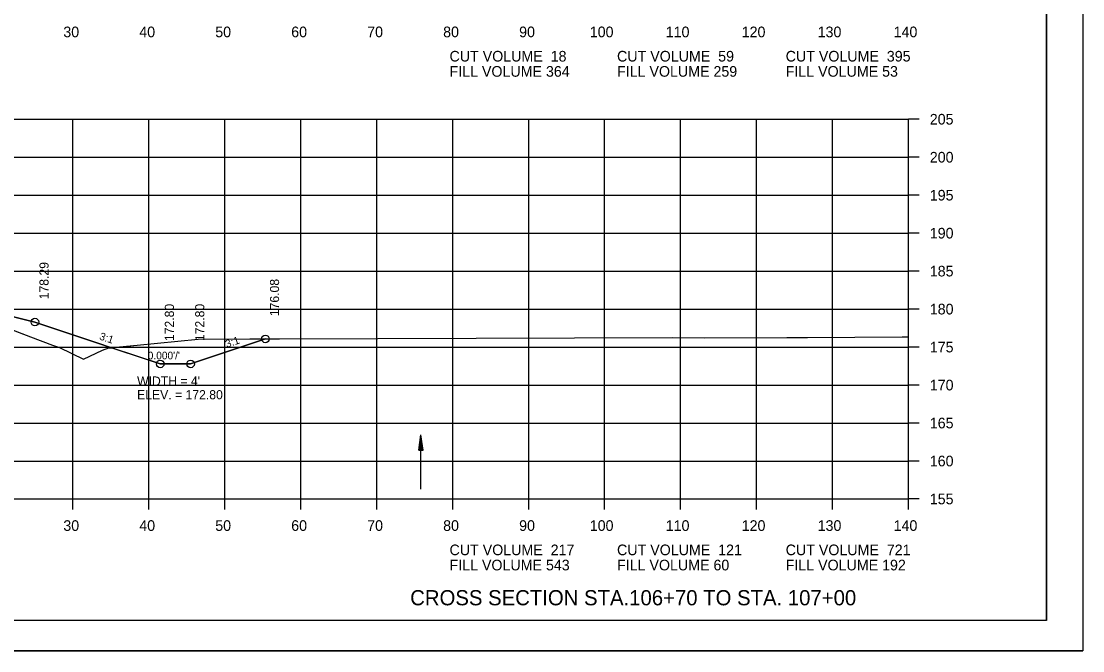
# Model space of a CAD drawing. Extents: x 1372132 to 1372465, y 380083 to 381790.
# Drawn here: x 1372325.2 to 1372464.9, y 380723.5 to 380806.4 of the extents above; entities that cross this region are included whole.
import ezdxf

# ---------------------------------------------------------------- set-up
doc = ezdxf.new("R2010")
doc.units = 0
for name, color, linetype in [('R_Axis', 7, 'Continuous'), ('R_Axis Annot', 7, 'Continuous'), ('R_Border', 7, 'Continuous'), ('R_Dimension', 7, 'Continuous'), ('R_Draft', 7, 'Continuous'), ('R_Exist Surface', 7, 'Continuous'), ('R_Fin Surface', 7, 'Continuous'), ('R_Grid', 7, 'Continuous'), ('R_No Plot', 7, 'Continuous'), ('R_Xsect Elev', 7, 'Continuous'), ('R_Xsect Slope', 7, 'Continuous')]:
    doc.layers.add(name, color=color, linetype=linetype)

msp = doc.modelspace()

# ---------------------------------------------------------------- linework, layer by layer
at = {"layer": 'R_Axis'}
for p, q in [((1372442.01, 380743.49), (1372442.01, 380793.49)), ((1372443.41, 380793.49), (1372442.01, 380793.49)), ((1372443.41, 380788.49), (1372442.01, 380788.49)), ((1372443.41, 380783.49), (1372442.01, 380783.49)), ((1372443.41, 380778.49), (1372442.01, 380778.49)), ((1372443.41, 380773.49), (1372442.01, 380773.49)), ((1372443.41, 380768.49), (1372442.01, 380768.49)), ((1372443.41, 380763.49), (1372442.01, 380763.49)), ((1372443.41, 380758.49), (1372442.01, 380758.49)), ((1372443.41, 380753.49), (1372442.01, 380753.49)), ((1372443.41, 380748.49), (1372442.01, 380748.49)), ((1372162.01, 380743.49), (1372442.01, 380743.49)), ((1372332.01, 380742.09), (1372332.01, 380743.49)), ((1372342.01, 380742.09), (1372342.01, 380743.49)), ((1372352.01, 380742.09), (1372352.01, 380743.49)), ((1372362.01, 380742.09), (1372362.01, 380743.49)), ((1372372.01, 380742.09), (1372372.01, 380743.49)), ((1372382.01, 380742.09), (1372382.01, 380743.49)), ((1372392.01, 380742.09), (1372392.01, 380743.49)), ((1372402.01, 380742.09), (1372402.01, 380743.49)), ((1372412.01, 380742.09), (1372412.01, 380743.49)), ((1372422.01, 380742.09), (1372422.01, 380743.49)), ((1372432.01, 380742.09), (1372432.01, 380743.49)), ((1372442.01, 380742.09), (1372442.01, 380743.49)), ((1372443.41, 380743.49), (1372442.01, 380743.49))]:
    msp.add_line(p, q, dxfattribs=at)
at = {"layer": 'R_Border'}
for q in [(1372460.19, 380932.95), (1372144.01, 380727.49)]:
    msp.add_line((1372460.19, 380727.49), q, dxfattribs=at)
at = {"layer": 'R_Dimension'}
for p, q in [((1372377.53, 380749.93), (1372377.83, 380751.93)), ((1372377.53, 380749.93), (1372377.83, 380751.93)), ((1372377.58, 380749.93), (1372377.83, 380751.6)), ((1372377.58, 380749.93), (1372377.83, 380751.6)), ((1372378.13, 380749.93), (1372377.83, 380751.93)), ((1372378.13, 380749.93), (1372377.83, 380751.93)), ((1372378.08, 380749.93), (1372377.83, 380751.6)), ((1372378.08, 380749.93), (1372377.83, 380751.6)), ((1372377.64, 380749.93), (1372377.83, 380751.25)), ((1372377.64, 380749.93), (1372377.83, 380751.25)), ((1372377.69, 380749.93), (1372377.83, 380750.92)), ((1372377.69, 380749.93), (1372377.83, 380750.92)), ((1372377.74, 380749.93), (1372377.83, 380750.58)), ((1372377.74, 380749.93), (1372377.83, 380750.58)), ((1372377.79, 380749.93), (1372377.83, 380750.25)), ((1372377.79, 380749.93), (1372377.83, 380750.25)), ((1372378.03, 380749.93), (1372377.83, 380751.25)), ((1372378.03, 380749.93), (1372377.83, 380751.25)), ((1372377.98, 380749.93), (1372377.83, 380750.92)), ((1372377.98, 380749.93), (1372377.83, 380750.92)), ((1372377.93, 380749.93), (1372377.83, 380750.58)), ((1372377.93, 380749.93), (1372377.83, 380750.58)), ((1372377.88, 380749.93), (1372377.83, 380750.25)), ((1372377.88, 380749.93), (1372377.83, 380750.25)), ((1372377.53, 380749.93), (1372378.13, 380749.93)), ((1372377.53, 380749.93), (1372378.13, 380749.93))]:
    msp.add_line(p, q, dxfattribs=at)
at = {"layer": 'R_Draft'}
msp.add_line((1372377.83, 380744.79), (1372377.83, 380751.93), dxfattribs=at)
at = {"layer": 'R_Exist Surface'}
msp.add_lwpolyline([(1372316.46, 380768.64), (1372326.44, 380764.85), (1372329.31, 380763.76), (1372330.26, 380763.44), (1372333.41, 380761.92), (1372335.9, 380763.07), (1372336.73, 380763.38), (1372340.45, 380763.74), (1372348.48, 380764.54), (1372355.29, 380764.56), (1372359.2, 380764.57), (1372410.98, 380764.76), (1372415.19, 380764.73), (1372425.99, 380764.77), (1372428.73, 380764.77), (1372441.16, 380764.82), (1372442.01, 380764.82)], dxfattribs=at)
at = {"layer": 'R_Fin Surface'}
msp.add_lwpolyline([(1372239.2, 380762.85), (1372244.03, 380761.25), (1372248.2, 380759.84), (1372256.2, 380759.84), (1372266.67, 380763.32), (1372277.01, 380766.78), (1372282.65, 380768.19), (1372287.01, 380769.28), (1372291.01, 380769.44), (1372302.01, 380769.66), (1372313.01, 380769.44), (1372317.01, 380769.28), (1372321.38, 380768.19), (1372327.01, 380766.78), (1372335.18, 380764.05), (1372343.51, 380761.28), (1372347.51, 380761.28), (1372352.36, 380762.91), (1372357.35, 380764.56)], dxfattribs=at)
at = {"layer": 'R_Grid'}
for p, q in [((1372162.01, 380793.49), (1372442.01, 380793.49)), ((1372332.01, 380743.49), (1372332.01, 380793.49)), ((1372342.01, 380743.49), (1372342.01, 380793.49)), ((1372352.01, 380743.49), (1372352.01, 380793.49)), ((1372362.01, 380743.49), (1372362.01, 380793.49)), ((1372372.01, 380743.49), (1372372.01, 380793.49)), ((1372382.01, 380743.49), (1372382.01, 380793.49)), ((1372392.01, 380743.49), (1372392.01, 380793.49)), ((1372402.01, 380743.49), (1372402.01, 380793.49)), ((1372412.01, 380743.49), (1372412.01, 380793.49)), ((1372422.01, 380743.49), (1372422.01, 380793.49)), ((1372432.01, 380743.49), (1372432.01, 380793.49)), ((1372442.01, 380743.49), (1372442.01, 380793.49)), ((1372162.01, 380788.49), (1372442.01, 380788.49)), ((1372162.01, 380783.49), (1372442.01, 380783.49)), ((1372162.01, 380778.49), (1372442.01, 380778.49)), ((1372162.01, 380773.49), (1372442.01, 380773.49)), ((1372162.01, 380768.49), (1372442.01, 380768.49)), ((1372162.01, 380763.49), (1372442.01, 380763.49)), ((1372162.01, 380758.49), (1372442.01, 380758.49)), ((1372162.01, 380753.49), (1372442.01, 380753.49)), ((1372162.01, 380748.49), (1372442.01, 380748.49)), ((1372162.01, 380743.49), (1372442.01, 380743.49))]:
    msp.add_line(p, q, dxfattribs=at)
at = {"layer": 'R_No Plot'}
msp.add_line((1372131.61, 380723.51), (1372464.95, 380723.51), dxfattribs=at)
for points in [[(1372131.61, 380936.84), (1372464.95, 380936.84), (1372464.95, 380723.5), (1372131.61, 380723.5)], [(1372377.93, 380932.95), (1372377.93, 380923.07), (1372413.67, 380923.07), (1372413.67, 380920.15), (1372436.87, 380920.15), (1372436.87, 380895.81), (1372460.19, 380895.81), (1372460.19, 380727.49), (1372144.01, 380727.49), (1372144.01, 380932.95)], [(1372317.43, 380768.27), (1372326.44, 380764.85), (1372329.31, 380763.76), (1372330.26, 380763.44), (1372333.41, 380761.92), (1372335.9, 380763.07), (1372336.73, 380763.38), (1372337.09, 380763.41), (1372335.18, 380764.05), (1372327.01, 380766.78), (1372321.38, 380768.19)], [(1372337.09, 380763.41), (1372340.45, 380763.74), (1372348.48, 380764.54), (1372355.29, 380764.56), (1372357.35, 380764.56), (1372352.36, 380762.91), (1372347.51, 380761.28), (1372343.51, 380761.28)]]:
    msp.add_lwpolyline(points, close=True, dxfattribs=at)
for centre in [(1372327.01, 380766.78), (1372357.35, 380764.56), (1372343.51, 380761.28), (1372347.51, 380761.28)]:
    msp.add_circle(centre, 0.5, dxfattribs=at)

# ---------------------------------------------------------------- texts
at = {"layer": 'R_Axis Annot'}
for s, p in [('30', (1372330.75, 380804.29)), ('40', (1372340.75, 380804.29)), ('50', (1372350.75, 380804.29)), ('60', (1372360.75, 380804.29)), ('70', (1372370.75, 380804.29)), ('80', (1372380.75, 380804.29)), ('90', (1372390.75, 380804.29)), ('100', (1372400.05, 380804.29)), ('110', (1372410.05, 380804.29)), ('120', (1372420.05, 380804.29)), ('130', (1372430.05, 380804.29)), ('140', (1372440.05, 380804.29)), ('CUT VOLUME  18', (1372381.59, 380801.09)), ('CUT VOLUME  59', (1372403.64, 380801.09)), ('CUT VOLUME  395', (1372425.84, 380801.09)), ('FILL VOLUME 364', (1372381.59, 380799.09)), ('FILL VOLUME 259', (1372403.64, 380799.09)), ('FILL VOLUME 53', (1372425.84, 380799.09)), ('205', (1372444.81, 380792.79)), ('200', (1372444.81, 380787.79)), ('195', (1372444.81, 380782.79)), ('190', (1372444.81, 380777.79)), ('185', (1372444.81, 380772.79)), ('180', (1372444.81, 380767.79)), ('175', (1372444.81, 380762.79)), ('170', (1372444.81, 380757.79)), ('165', (1372444.81, 380752.79)), ('160', (1372444.81, 380747.79)), ('155', (1372444.81, 380742.79)), ('30', (1372330.75, 380739.29)), ('40', (1372340.75, 380739.29)), ('50', (1372350.75, 380739.29)), ('60', (1372360.75, 380739.29)), ('70', (1372370.75, 380739.29)), ('80', (1372380.75, 380739.29)), ('90', (1372390.75, 380739.29)), ('100', (1372400.05, 380739.29)), ('110', (1372410.05, 380739.29)), ('120', (1372420.05, 380739.29)), ('130', (1372430.05, 380739.29)), ('140', (1372440.05, 380739.29)), ('CUT VOLUME  217', (1372381.59, 380736.09)), ('CUT VOLUME  121', (1372403.64, 380736.09)), ('CUT VOLUME  721', (1372425.84, 380736.09)), ('FILL VOLUME 543', (1372381.59, 380734.09)), ('FILL VOLUME 60', (1372403.64, 380734.09)), ('FILL VOLUME 192', (1372425.84, 380734.09))]:
    msp.add_text(s, height=1.4, dxfattribs=at).set_placement(p)
at = {"layer": 'R_Dimension'}
for s, p in [("WIDTH = 4'", (1372340.46, 380758.42)), ('ELEV. = 172.80', (1372340.46, 380756.62))]:
    msp.add_text(s, height=1.2, dxfattribs=at).set_placement(p)
at = {"layer": 'R_Draft'}
msp.add_text('CROSS SECTION STA.106+70 TO STA. 107+00', height=2, dxfattribs=at).set_placement((1372376.41, 380729.49))
at = {"layer": 'R_Xsect Elev'}
for s, p in [('178.29', (1372328.81, 380769.78)), ('176.08', (1372359.15, 380767.56)), ('172.80', (1372345.31, 380764.28)), ('172.80', (1372349.31, 380764.28))]:
    msp.add_text(s, height=1.2, rotation=90, dxfattribs=at).set_placement(p)
at = {"layer": 'R_Xsect Slope'}
for s, rotation, p in [('3:1', 341.5668, (1372335.42, 380764.51)), ('3:1', 18.4349, (1372352.27, 380763.4)), ("0.000'/'", 360, (1372341.86, 380761.88))]:
    msp.add_text(s, height=1, rotation=rotation, dxfattribs=at).set_placement(p)

doc.saveas('drawing.dxf')
